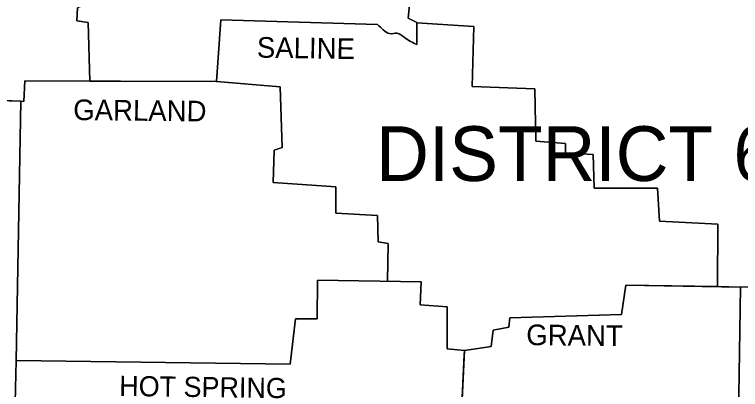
# Model space of a CAD drawing. Extents: x 1370567 to 1373900, y 377514 to 379648.
# Drawn here: x 1373319.4 to 1373477.5, y 379054.3 to 379135.9 of the extents above; entities that cross this region are included whole.
import ezdxf

# ---------------------------------------------------------------- set-up
doc = ezdxf.new("R2010")
doc.units = 0
doc.layers.add('Survey Names', color=7, linetype='Continuous')
doc.layers.add('Survey Symbols', color=7, linetype='Continuous')

msp = doc.modelspace()

# ---------------------------------------------------------------- linework, layer by layer
at = {"layer": 'Survey Names'}
msp.add_line((1373320.81, 379116.97), (1373319.59, 379051.41), dxfattribs=at)
for points in [[(1373440.05, 379149.65), (1373432.53, 379150.49), (1373432.84, 379147.67), (1373419.16, 379147.15), (1373418.75, 379143.08), (1373405.9, 379142.35), (1373405.17, 379135.04), (1373407.05, 379134.1), (1373407.05, 379129.3)], [(1373333.13, 379137.33), (1373333.02, 379134.52), (1373335.43, 379134.1), (1373335.86, 379121.39)], [(1373398.49, 379133.68), (1373364.35, 379134.72), (1373363.41, 379121.26), (1373321.64, 379121.46), (1373321.47, 379116.95)], [(1373407.05, 379134.04), (1373419.48, 379133.26), (1373419.06, 379120.21), (1373432.74, 379119.69), (1373432.95, 379108.31), (1373439.42, 379107.79), (1373439.42, 379105.8), (1373445.48, 379105.39), (1373445.68, 379098.08), (1373459.47, 379098.08), (1373459.88, 379090.87), (1373472.62, 379090.25), (1373472.52, 379076.65)], [(1373363.41, 379121.26), (1373377.3, 379120.11), (1373377.71, 379106.95), (1373375.94, 379106.33), (1373375.73, 379099.33), (1373389.41, 379098.39), (1373389.41, 379092.65), (1373398.49, 379092.13), (1373398.6, 379086.38), (1373400.79, 379086.07), (1373400.68, 379077.82)], [(1373320.81, 379116.97), (1373279.88, 379118.54)], [(1373321.47, 379116.95), (1373320.81, 379116.97)], [(1373319.76, 379060.59), (1373379.49, 379059.76), (1373380.64, 379069.68), (1373385.33, 379069.68), (1373385.44, 379078.03), (1373407.99, 379077.72), (1373407.78, 379072.71), (1373413.63, 379072.29), (1373413.63, 379063.1), (1373417.39, 379062.79), (1373417.35, 379061.83)], [(1373417.39, 379062.79), (1373423.24, 379063.62), (1373423.65, 379067.17), (1373427.1, 379067.8), (1373427.31, 379069.89), (1373451.64, 379070.62), (1373452.58, 379076.99), (1373477.53, 379076.57)], [(1373477.53, 379076.57), (1373476.9, 379034.18), (1373474.5, 379034.07), (1373474.19, 379007.87)], [(1373417.39, 379062.79), (1373416.14, 379035.43), (1373415.2, 379035.74), (1373415.3, 379021.66)]]:
    msp.add_lwpolyline(points, dxfattribs=at)
msp.add_spline([(1373407.05, 379129.3), (1373404.34, 379130.86), (1373402.77, 379131.8), (1373401.1, 379131.7), (1373399.74, 379132.53), (1373398.49, 379133.68)], degree=3, dxfattribs=at)
at = {"layer": 'Survey Symbols'}
for p, q in [((1373407.05, 379134.04), (1373407.05, 379129.3)), ((1373407.05, 379134.04), (1373419.48, 379133.26)), ((1373419.48, 379133.26), (1373419.06, 379120.21)), ((1373321.64, 379121.46), (1373321.47, 379116.95)), ((1373279.88, 379118.54), (1373320.81, 379116.97)), ((1373320.81, 379116.97), (1373279.88, 379118.54)), ((1373320.81, 379116.97), (1373319.76, 379060.59)), ((1373320.81, 379116.97), (1373321.47, 379116.95)), ((1373321.47, 379116.95), (1373320.81, 379116.97)), ((1373432.95, 379108.31), (1373439.42, 379107.79)), ((1373439.42, 379107.79), (1373439.42, 379105.8)), ((1373439.42, 379105.8), (1373445.48, 379105.39)), ((1373445.48, 379105.39), (1373445.68, 379098.08)), ((1373398.6, 379086.38), (1373400.79, 379086.07)), ((1373400.79, 379086.07), (1373400.68, 379077.82)), ((1373472.52, 379076.65), (1373477.53, 379076.57)), ((1373477.53, 379076.57), (1373500.6, 379076.66)), ((1373319.76, 379060.59), (1373319.59, 379051.41))]:
    msp.add_line(p, q, dxfattribs=at)
for points in [[(1373407.05, 379129.3), (1373407.05, 379134.1), (1373405.17, 379135.04), (1373405.9, 379142.35), (1373418.75, 379143.08), (1373419.16, 379147.15), (1373432.84, 379147.67), (1373432.53, 379150.49), (1373432.76, 379150.46)], [(1373440.05, 379149.65), (1373432.76, 379150.46), (1373432.53, 379150.49), (1373432.84, 379147.67), (1373419.16, 379147.15), (1373418.75, 379143.08), (1373405.9, 379142.35), (1373405.17, 379135.04), (1373407.05, 379134.1), (1373407.05, 379134.04)], [(1373339.6, 379142.66), (1373337.41, 379142.03), (1373336.89, 379139.21), (1373335.22, 379139.32), (1373334.7, 379137.86), (1373333.13, 379137.33), (1373333.02, 379134.52)], [(1373335.86, 379121.39), (1373335.43, 379134.1), (1373333.02, 379134.52), (1373333.13, 379137.33)], [(1373333.02, 379134.52), (1373335.43, 379134.1), (1373335.86, 379121.39)], [(1373335.86, 379121.39), (1373363.41, 379121.26), (1373364.35, 379134.72), (1373398.49, 379133.68)], [(1373398.49, 379133.68), (1373364.35, 379134.72), (1373363.41, 379121.26)], [(1373472.52, 379076.65), (1373472.62, 379090.25), (1373459.88, 379090.87), (1373459.47, 379098.08), (1373445.68, 379098.08), (1373445.48, 379105.39), (1373439.42, 379105.8), (1373439.42, 379107.79), (1373432.95, 379108.31), (1373432.74, 379119.69), (1373419.06, 379120.21), (1373419.48, 379133.26), (1373407.05, 379134.04)], [(1373321.47, 379116.95), (1373321.64, 379121.46), (1373335.86, 379121.39)], [(1373363.41, 379121.26), (1373335.86, 379121.39), (1373321.64, 379121.46)], [(1373400.68, 379077.82), (1373400.79, 379086.07), (1373398.6, 379086.38), (1373398.49, 379092.13), (1373389.41, 379092.65), (1373389.41, 379098.39), (1373375.73, 379099.33), (1373375.94, 379106.33), (1373377.71, 379106.95), (1373377.3, 379120.11), (1373363.41, 379121.26)], [(1373363.41, 379121.26), (1373377.3, 379120.11), (1373377.71, 379106.95)], [(1373419.06, 379120.21), (1373432.74, 379119.69), (1373432.95, 379108.31)], [(1373319.59, 379051.41), (1373319.76, 379060.59), (1373320.81, 379116.97)], [(1373377.71, 379106.95), (1373375.94, 379106.33), (1373375.73, 379099.33), (1373389.41, 379098.39)], [(1373389.41, 379098.39), (1373389.41, 379092.65), (1373398.49, 379092.13), (1373398.6, 379086.38)], [(1373445.68, 379098.08), (1373459.47, 379098.08), (1373459.88, 379090.87)], [(1373459.88, 379090.87), (1373472.62, 379090.25), (1373472.52, 379076.65)], [(1373417.39, 379062.79), (1373413.63, 379063.1), (1373413.63, 379072.29), (1373407.78, 379072.71), (1373407.99, 379077.72), (1373385.44, 379078.03), (1373385.33, 379069.68), (1373380.64, 379069.68), (1373379.49, 379059.76), (1373319.76, 379060.59)], [(1373319.76, 379060.59), (1373379.49, 379059.76), (1373380.64, 379069.68), (1373385.33, 379069.68), (1373385.44, 379078.03), (1373400.68, 379077.82)], [(1373400.68, 379077.82), (1373407.99, 379077.72), (1373407.78, 379072.71), (1373413.63, 379072.29), (1373413.63, 379063.1), (1373417.39, 379062.79)], [(1373477.53, 379076.57), (1373472.52, 379076.65), (1373452.58, 379076.99), (1373451.64, 379070.62), (1373427.31, 379069.89), (1373427.1, 379067.8), (1373423.65, 379067.17), (1373423.24, 379063.62), (1373417.39, 379062.79)], [(1373417.39, 379062.79), (1373423.24, 379063.62), (1373423.65, 379067.17), (1373427.1, 379067.8), (1373427.31, 379069.89), (1373451.64, 379070.62), (1373452.58, 379076.99), (1373472.52, 379076.65)], [(1373474.19, 379007.87), (1373474.5, 379034.07), (1373476.9, 379034.18), (1373477.53, 379076.57)], [(1373477.53, 379076.57), (1373476.9, 379034.18), (1373474.5, 379034.07)], [(1373543.76, 379076.83), (1373500.6, 379076.66), (1373477.53, 379076.57)], [(1373417.39, 379062.79), (1373417.35, 379061.83), (1373416.14, 379035.43), (1373415.2, 379035.74), (1373415.3, 379021.66)], [(1373415.2, 379035.74), (1373416.14, 379035.43), (1373417.35, 379061.83), (1373417.39, 379062.79)], [(1373319.76, 379060.59), (1373319.76, 379060.59)]]:
    msp.add_lwpolyline(points, dxfattribs=at)
for points in [[(1373398.49, 379133.68), (1373399.74, 379132.53), (1373401.1, 379131.7), (1373402.77, 379131.8), (1373404.34, 379130.86), (1373407.05, 379129.3)], [(1373407.05, 379129.3), (1373404.34, 379130.86), (1373402.77, 379131.8), (1373401.1, 379131.7), (1373399.74, 379132.53), (1373398.49, 379133.68)]]:
    msp.add_spline(points, degree=3, dxfattribs=at)

# ---------------------------------------------------------------- texts
at = {"layer": 'Survey Names'}
for s, height, rotation, p in [('SALINE', 4.49, 359.1492, (1373372.18, 379126.48)), ('GARLAND', 4.49, 359.3658, (1373332.19, 379112.9)), ('GRANT', 4.49, 359.4032, (1373430.86, 379063.93)), ('HOT SPRING', 4.386, 359.2216, (1373342.21, 379052.87))]:
    msp.add_text(s, height=height, rotation=rotation, dxfattribs=at).set_placement(p)
msp.add_text('DISTRICT 6', height=11.903, dxfattribs=at).set_placement((1373398.18, 379099.64))

doc.saveas('drawing.dxf')
